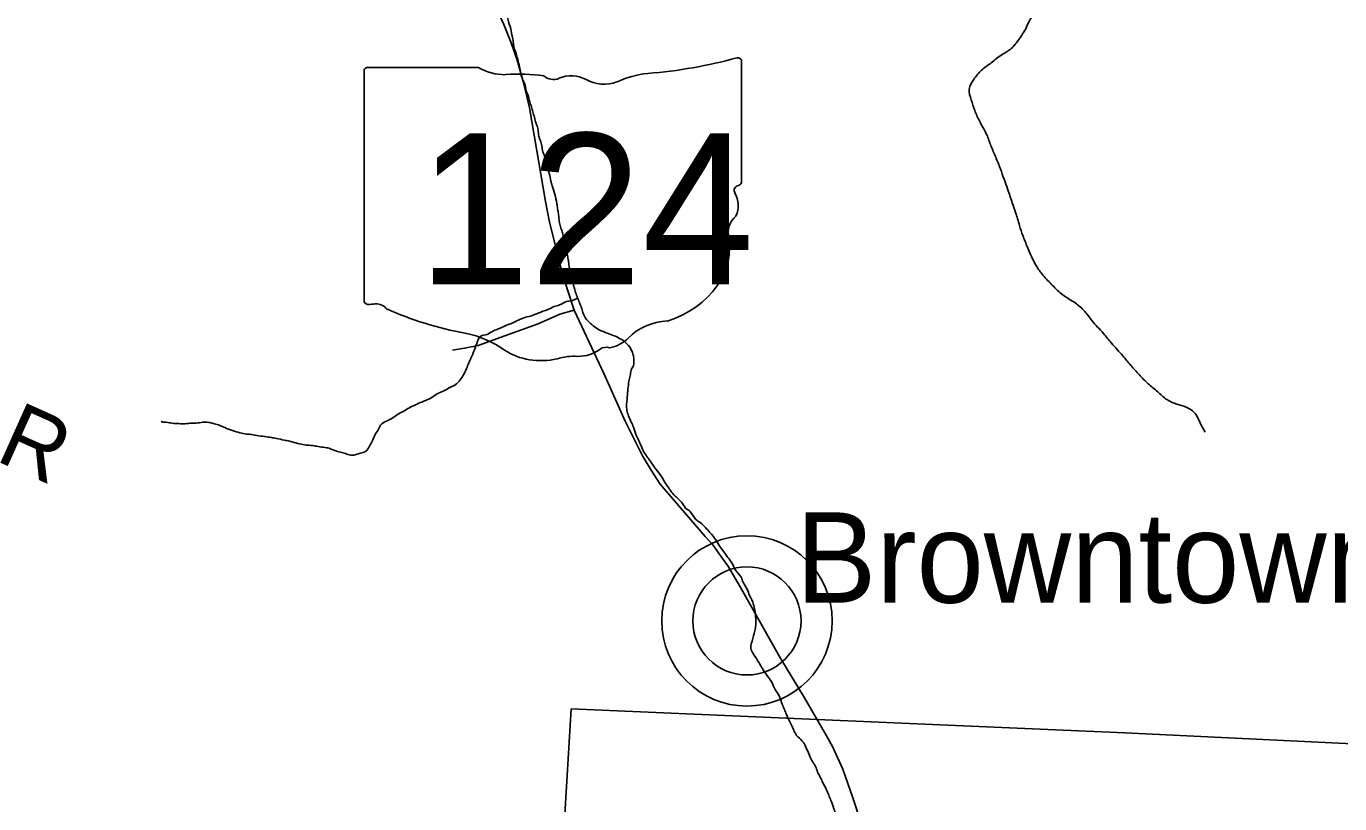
# Model space of a CAD drawing. Extents: x -20.2 to 34, y 0 to 22.
# Drawn here: x 5.177 to 6.324, y 14.901 to 15.58 of the extents above; entities that cross this region are included whole.
import ezdxf

# ---------------------------------------------------------------- set-up
doc = ezdxf.new("R2010")
doc.units = 0
for name, color, linetype in [('Default', 7, 'Continuous'), ('GM_X_Minor_River', 7, 'Continuous'), ('GM_X_State_Location', 7, 'Continuous'), ('GM_X_State_Route', 7, 'Continuous'), ('GM_X_State_Shield', 7, 'Continuous'), ('GM_X_Township_Road', 7, 'Continuous'), ('GM_X_Township_Road_Text', 7, 'Continuous'), ('GM_X_Unincorporated', 7, 'Continuous'), ('GM_X_Unincorporated_Location', 7, 'Continuous'), ('GM_X_Unincorporated_Text', 7, 'Continuous')]:
    doc.layers.add(name, color=color, linetype=linetype)

msp = doc.modelspace()

# ---------------------------------------------------------------- linework, layer by layer
at = {"layer": 'Default'}
msp.add_lwpolyline([(6.028, 14.1), (6.6784, 14.1), (6.7274, 14.9346), (6.1367, 14.9631), (5.6533, 14.9839), (5.6384, 14.7364), (5.6162, 14.3582), (5.6005, 14.1269), (5.6278, 14.1271), (5.6498, 14.1279), (5.6733, 14.1303), (5.6861, 14.1307), (5.7161, 14.1317), (5.7513, 14.1295), (5.7847, 14.1278), (5.812, 14.1272), (5.8226, 14.1261), (5.8415, 14.1258), (5.8745, 14.1203), (5.9022, 14.1151), (5.9363, 14.1115), (5.9579, 14.1082), (5.9833, 14.1072), (6.0148, 14.1032)], close=True, dxfattribs=at)
at = {"layer": 'GM_X_Minor_River'}
for points in [[(6.3228, 15.8584), (6.3171, 15.8573), (6.3088, 15.8554), (6.2977, 15.8491), (6.2916, 15.84), (6.2851, 15.8298), (6.2789, 15.8196), (6.2739, 15.8117), (6.2697, 15.8037), (6.2639, 15.7947), (6.2555, 15.786), (6.2463, 15.7796), (6.238, 15.7755), (6.2292, 15.7733), (6.2201, 15.7711), (6.2121, 15.7639), (6.2037, 15.7633), (6.1954, 15.7645), (6.1874, 15.7645), (6.1783, 15.7627), (6.1692, 15.7593), (6.1612, 15.7541), (6.1493, 15.7417), (6.1435, 15.7337), (6.1378, 15.7247), (6.132, 15.7167), (6.1259, 15.7077), (6.1217, 15.6997), (6.117, 15.6892), (6.1128, 15.6805), (6.1104, 15.6706), (6.1062, 15.6604), (6.1027, 15.6524), (6.0962, 15.6441), (6.0897, 15.6362), (6.082, 15.6238), (6.0743, 15.6151), (6.0671, 15.6049), (6.0609, 15.5951), (6.0544, 15.5868), (6.0505, 15.5788), (6.044, 15.5686), (6.0375, 15.5607), (6.0295, 15.5555), (6.02, 15.5483), (6.0116, 15.5419), (6.0047, 15.5336), (6.0008, 15.5253), (6.0026, 15.5158), (6.0056, 15.5067), (6.0097, 15.4975), (6.0161, 15.4853), (6.0198, 15.4758), (6.0239, 15.4659), (6.028, 15.4556), (6.0313, 15.4465), (6.0343, 15.4381), (6.0384, 15.4259), (6.0413, 15.4176), (6.0447, 15.4062), (6.0476, 15.3974), (6.0517, 15.3871), (6.0592, 15.3711), (6.0652, 15.3627), (6.0735, 15.3539), (6.0825, 15.3455), (6.092, 15.3394), (6.1007, 15.3321), (6.1078, 15.3233), (6.118, 15.3118), (6.1251, 15.3034), (6.1349, 15.2923), (6.142, 15.2839), (6.1492, 15.2759), (6.1571, 15.2679), (6.1654, 15.261), (6.1733, 15.2541), (6.182, 15.2502), (6.1903, 15.2475), (6.1983, 15.2417), (6.2024, 15.2337), (6.2069, 15.2257)], [(5.7529, 15.1594), (5.7495, 15.1644), (5.7409, 15.1732), (5.7382, 15.1773), (5.7349, 15.1819), (5.7319, 15.1873), (5.7274, 15.193), (5.7232, 15.1991), (5.7202, 15.2033), (5.7168, 15.2083), (5.7142, 15.2136), (5.7124, 15.2182), (5.7101, 15.2231), (5.7075, 15.23), (5.7057, 15.2345), (5.7034, 15.2399), (5.7019, 15.2448), (5.7016, 15.2494), (5.702, 15.2539), (5.7024, 15.2592), (5.7028, 15.2634), (5.7037, 15.2702), (5.7048, 15.2748), (5.7056, 15.2797), (5.7075, 15.2839), (5.708, 15.2888), (5.7072, 15.2938), (5.7043, 15.2999), (5.6997, 15.3048), (5.6948, 15.3079), (5.6899, 15.3102), (5.6839, 15.3125), (5.6789, 15.3145), (5.6737, 15.3176), (5.6688, 15.3218), (5.665, 15.3264), (5.6631, 15.3313), (5.6616, 15.3359), (5.6598, 15.3404), (5.6579, 15.3454), (5.6564, 15.35), (5.6553, 15.3541), (5.6542, 15.3587), (5.6528, 15.364), (5.6517, 15.369), (5.6509, 15.3743), (5.6502, 15.3789), (5.6491, 15.383), (5.6484, 15.3876), (5.6473, 15.3925), (5.6458, 15.3986), (5.6447, 15.4028), (5.6432, 15.4074), (5.6425, 15.4123), (5.6421, 15.4165), (5.6414, 15.4207), (5.6407, 15.4252), (5.6389, 15.4336), (5.6366, 15.4408), (5.6355, 15.445), (5.6341, 15.4515), (5.6322, 15.4576), (5.63, 15.4667), (5.6281, 15.4717), (5.6274, 15.477), (5.6259, 15.4812), (5.6248, 15.4853), (5.6241, 15.491), (5.6226, 15.4952), (5.6212, 15.5009), (5.6197, 15.5055), (5.6186, 15.5097), (5.6171, 15.5143), (5.616, 15.5188), (5.6137, 15.5245), (5.613, 15.5287), (5.61, 15.5359), (5.6089, 15.5401), (5.6082, 15.5447), (5.6064, 15.5519), (5.6053, 15.5561), (5.6034, 15.5614), (5.6027, 15.5664), (5.6016, 15.5717), (5.6009, 15.5759), (5.5986, 15.5842), (5.5975, 15.5892), (5.5968, 15.5934), (5.5961, 15.5995), (5.5954, 15.6036), (5.5954, 15.6127), (5.5955, 15.6173), (5.5967, 15.6234), (5.5978, 15.629), (5.599, 15.634), (5.6002, 15.6381), (5.601, 15.6427)], [(5.6588, 15.343), (5.6537, 15.3405), (5.6492, 15.3398), (5.6431, 15.3368), (5.6385, 15.3353), (5.6328, 15.3327), (5.6286, 15.3312), (5.6237, 15.3293), (5.6176, 15.3271), (5.6122, 15.3256), (5.6077, 15.3238), (5.6004, 15.3204), (5.5955, 15.3185), (5.589, 15.3156), (5.5844, 15.3137), (5.5799, 15.3111), (5.5742, 15.3096), (5.5715, 15.3051), (5.5657, 15.2903), (5.5638, 15.2861), (5.5618, 15.2812), (5.5564, 15.2714), (5.5518, 15.2669), (5.5473, 15.2646), (5.5427, 15.262), (5.5374, 15.2598), (5.5324, 15.2564), (5.5263, 15.2534), (5.5217, 15.2515), (5.516, 15.2489), (5.5107, 15.2463), (5.5065, 15.2437), (5.5016, 15.2411), (5.4966, 15.2377), (5.492, 15.2354), (5.4867, 15.2317), (5.4844, 15.2272), (5.4817, 15.223), (5.4794, 15.2177), (5.4771, 15.2135), (5.474, 15.209), (5.469, 15.2072), (5.4633, 15.2057), (5.4584, 15.2061), (5.4539, 15.2077), (5.4493, 15.2088), (5.4429, 15.2112), (5.4383, 15.2123), (5.4323, 15.2131), (5.4277, 15.2139), (5.4232, 15.2143), (5.4175, 15.2151), (5.4114, 15.2167), (5.4073, 15.2179), (5.4027, 15.2187), (5.3959, 15.2202), (5.3914, 15.221), (5.3861, 15.2218), (5.3819, 15.2223), (5.3754, 15.2234), (5.3709, 15.2239), (5.3656, 15.2247), (5.3592, 15.2266), (5.3523, 15.2289), (5.3463, 15.2316), (5.3417, 15.2328), (5.3376, 15.234), (5.333, 15.2344), (5.3273, 15.2337), (5.3205, 15.2334), (5.3163, 15.233), (5.3106, 15.2331), (5.3049, 15.2335), (5.2996, 15.2343), (5.2951, 15.2347)], [(6.0123, 14.6828), (6.0257, 14.7028), (6.0273, 14.707), (6.0273, 14.7119), (6.0247, 14.7168), (6.0225, 14.7214), (6.0198, 14.7256), (6.0149, 14.7298), (6.0104, 14.7329), (6.0055, 14.7329), (6.0005, 14.7318), (5.9956, 14.7326), (5.9865, 14.7342), (5.9816, 14.7354), (5.977, 14.7366), (5.9729, 14.7385), (5.9676, 14.7435), (5.9642, 14.7477), (5.9612, 14.7519), (5.9586, 14.7561), (5.9567, 14.7603), (5.953, 14.766), (5.9507, 14.7702), (5.9473, 14.7744), (5.944, 14.779), (5.9413, 14.7832), (5.9379, 14.7878), (5.9342, 14.7924), (5.9319, 14.7965), (5.9282, 14.8008), (5.9244, 14.8061), (5.921, 14.8107), (5.9188, 14.8153), (5.9162, 14.8195), (5.9143, 14.824), (5.9106, 14.8294), (5.9083, 14.8343), (5.9057, 14.8385), (5.9027, 14.8439), (5.9012, 14.848), (5.8997, 14.8534), (5.896, 14.861), (5.8945, 14.8656), (5.8923, 14.8709), (5.8901, 14.8777), (5.8878, 14.8819), (5.8863, 14.8865), (5.8845, 14.8915), (5.8826, 14.8968), (5.88, 14.904), (5.8781, 14.9086), (5.8759, 14.9139), (5.8729, 14.9196), (5.871, 14.9238), (5.8684, 14.9288), (5.8666, 14.9337), (5.8639, 14.9379), (5.8617, 14.9425), (5.8591, 14.9486), (5.855, 14.9559), (5.8501, 14.9608), (5.8475, 14.9654), (5.8452, 14.9704), (5.843, 14.9749), (5.8407, 14.9803), (5.8389, 14.9845), (5.837, 14.9894), (5.8348, 14.9955), (5.8314, 15.0008), (5.828, 15.0077), (5.8235, 15.0142), (5.8202, 15.0192), (5.8142, 15.0291), (5.8115, 15.0333), (5.81, 15.0378), (5.8112, 15.0431), (5.8136, 15.0522), (5.8144, 15.0572), (5.8144, 15.0617), (5.8141, 15.067), (5.813, 15.0727), (5.8111, 15.0788), (5.8089, 15.083), (5.807, 15.0884), (5.8033, 15.0945), (5.8018, 15.0986), (5.7969, 15.1048), (5.7939, 15.1109), (5.7901, 15.1162), (5.7864, 15.1212), (5.783, 15.1257), (5.7796, 15.1315), (5.7744, 15.138), (5.7661, 15.1464), (5.7619, 15.1498), (5.7571, 15.1563), (5.7529, 15.1594)]]:
    msp.add_spline(points, degree=3, dxfattribs=at)
at = {"layer": 'GM_X_State_Route'}
for points in [[(5.587, 15.5975), (5.5944, 15.5816), (5.6009, 15.5658), (5.6062, 15.5505), (5.612, 15.53), (5.6169, 15.5089), (5.6309, 15.4271), (5.6343, 15.409), (5.6401, 15.3861), (5.6438, 15.3703), (5.6497, 15.3508), (5.6559, 15.3322)], [(5.6559, 15.3322), (5.682, 15.2763), (5.7004, 15.2353), (5.7155, 15.2049), (5.723, 15.1924), (5.7308, 15.1803), (5.7702, 15.1344), (5.777, 15.1273), (5.7825, 15.1195), (5.7907, 15.108), (5.8018, 15.0884), (5.8354, 15.0291), (5.8569, 14.9936), (5.8751, 14.9625), (5.8815, 14.9512), (5.8904, 14.9312), (5.8991, 14.9062), (5.9142, 14.8604)]]:
    msp.add_lwpolyline(points, dxfattribs=at)
at = {"layer": 'GM_X_State_Shield'}
for p, q in [((5.4724, 15.5409), (5.4724, 15.3407)), ((5.5722, 15.5443), (5.4757, 15.5443)), ((5.802, 15.4446), (5.802, 15.5493)), ((5.802, 15.4446), (5.802, 15.4446))]:
    msp.add_line(p, q, dxfattribs=at)
for centre, major_axis, start_param, end_param in [((5.6846, 15.8171), (0.3495, 0), 4.814394, 5.042369), ((5.7984, 15.5497), (0.00367, 0), 6.141152, 7.989035), ((5.4762, 15.5413), (0.00382, 0), 1.712693, 3.28349), ((5.5952, 15.5675), (0.037, 0), 4.042523, 4.731795), ((5.6075, 15.432), (0.133, 0), 1.404758, 1.657858), ((5.6377, 15.5423), (0.0107, 0), 3.836095, 5.185415), ((5.6533, 15.5192), (0.0222, 0), 0.950623, 2.079405), ((5.682, 15.5509), (0.0267, 0), 4.081561, 5.145723), ((5.7292, 15.4832), (0.0703, 0), 1.699011, 2.107814), ((5.8012, 15.4369), (0.00568, 0), 1.883978, 3.671073), ((5.7981, 15.4442), (0.00393, 0), 5.05454, 6.418171), ((5.765, 15.4237), (0.0341, 0), 5.934695, 6.695948), ((5.8152, 15.4008), (0.0248, 0), 2.387724, 3.262537), ((5.7042, 15.3874), (0.0874, 0), 5.101752, 6.440018), ((5.4762, 15.3403), (0.00385, 0), 3.00124, 4.508301), ((5.4768, 15.3608), (0.0294, 0), 4.665946, 4.897461), ((5.4828, 15.3292), (0.0106, 0), 0.519207, 1.627899), ((5.6167, 15.509), (0.2524, 0), 4.195997, 4.488961), ((5.7411, 15.2846), (0.0479, 0), 1.647645, 2.488434), ((5.5414, 15.2508), (0.079, 0), 0.823519, 1.323587), ((5.6836, 15.2938), (0.00752, 0), 1.147584, 2.315152), ((5.6804, 15.3213), (0.0282, 0), 4.937069, 5.64225), ((5.6268, 15.3282), (0.0501, 0), 4.026481, 4.996735), ((5.6558, 15.259), (0.0412, 0), 1.495662, 1.94098), ((5.6594, 15.3132), (0.0267, 0), 4.691044, 5.507374)]:
    msp.add_ellipse(centre, major_axis=major_axis, ratio=0.8, start_param=start_param, end_param=end_param, dxfattribs=at)
at = {"layer": 'GM_X_Township_Road'}
msp.add_lwpolyline([(5.6559, 15.3322), (5.6433, 15.3287), (5.6245, 15.3204), (5.5954, 15.3099), (5.5721, 15.3014), (5.5602, 15.299), (5.5496, 15.2974)], dxfattribs=at)
at = {"layer": 'GM_X_Unincorporated'}
for radius in [0.0744, 0.0472]:
    msp.add_circle((5.8067, 15.0608), radius, dxfattribs=at)
at = {"layer": 'GM_X_Unincorporated_Location'}
msp.add_line((5.8067, 15.0608), (5.8067, 15.0608), dxfattribs=at)

# ---------------------------------------------------------------- texts
at = {"layer": 'GM_X_State_Location'}
for s in ['s', 'r']:
    msp.add_text(s, height=0.000189, dxfattribs=at).set_placement((5.6335, 15.4275))
msp.add_text('124', height=0.000189, rotation=0, dxfattribs=at).set_placement((5.5667, 15.4137))
at = {"layer": 'GM_X_State_Shield'}
msp.add_text('124', height=0.13184, dxfattribs=at).set_placement((5.519, 15.3548))
at = {"layer": 'GM_X_Township_Road_Text'}
msp.add_text('R', height=0.0568, rotation=335.8463, dxfattribs=at).set_placement((5.1491, 15.2015))
at = {"layer": 'GM_X_Unincorporated_Text'}
msp.add_text('Browntown', height=0.07898, rotation=0, dxfattribs=at).set_placement((5.8492, 15.0767))

doc.saveas('drawing.dxf')
